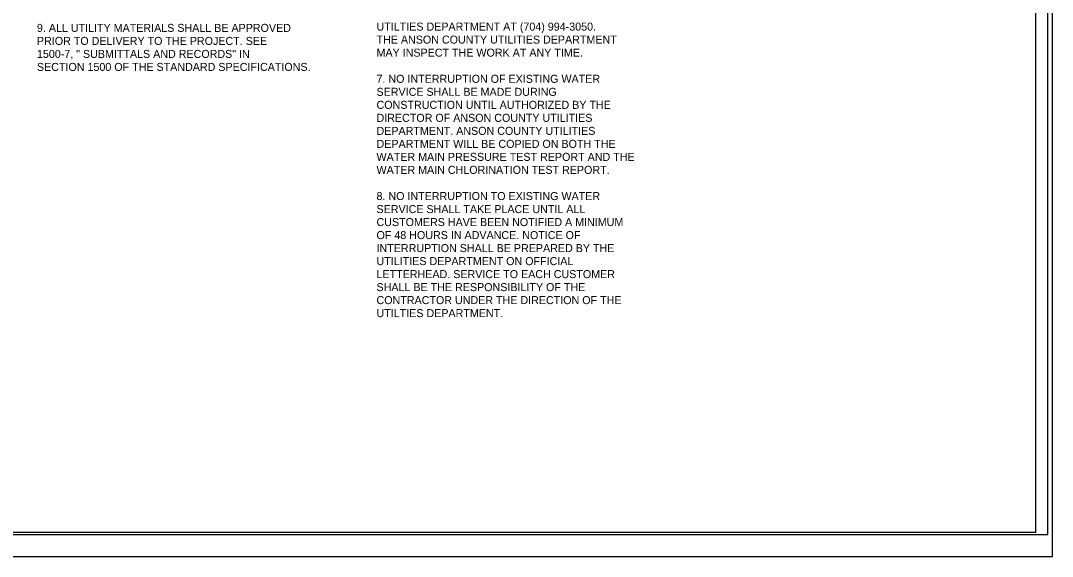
# Model space of a CAD drawing. Extents: x 0 to 674, y 0 to 440.
# Drawn here: x 248.2 to 673.6, y 0 to 220.9 of the extents above; entities that cross this region are included whole.
import ezdxf

# ---------------------------------------------------------------- set-up
doc = ezdxf.new("R2010")
doc.units = 0
for name, color, linetype in [('General Text and Text Box and Leader Line', 7, 'Continuous'), ('Sheet Plot Border Inside CELL', 7, 'Continuous'), ('Sheet Plot Border Outside CELL', 7, 'Continuous'), ('UC Notes and Details Sheet 34 CELL', 7, 'Continuous')]:
    doc.layers.add(name, color=color, linetype=linetype)

msp = doc.modelspace()

# ---------------------------------------------------------------- linework, layer by layer
at = {"layer": 'Sheet Plot Border Inside CELL'}
msp.add_lwpolyline([(671.8, 431.01), (5.2, 431.01), (5.2, 8.97), (671.8, 8.97)], close=True, dxfattribs=at)
at = {"layer": 'Sheet Plot Border Outside CELL'}
msp.add_lwpolyline([(673.6, 440), (0, 440), (0, 0), (673.6, 0)], close=True, dxfattribs=at)
at = {"layer": 'UC Notes and Details Sheet 34 CELL'}
msp.add_lwpolyline([(666.8, 430), (66.8, 430), (66.8, 10), (666.8, 10)], close=True, dxfattribs=at)

# ---------------------------------------------------------------- texts
at = {"layer": 'General Text and Text Box and Leader Line'}
for s, p in [('9. ALL UTILITY MATERIALS SHALL BE APPROVED ', (254.96, 216.22)), ('UTILTIES DEPARTMENT AT (704) 994-3050. ', (394.96, 216.75)), ('PRIOR TO DELIVERY TO THE PROJECT. SEE ', (254.96, 210.85)), ('THE ANSON COUNTY UTILITIES DEPARTMENT ', (394.96, 211.39)), ('1500-7, " SUBMITTALS AND RECORDS" IN ', (254.96, 205.49)), ('MAY INSPECT THE WORK AT ANY TIME.', (394.96, 206.02)), ('SECTION 1500 OF THE STANDARD SPECIFICATIONS.', (254.96, 200.13)), ('7. NO INTERRUPTION OF EXISTING WATER ', (394.96, 195.22)), ('SERVICE SHALL BE MADE DURING ', (394.96, 189.86)), ('CONSTRUCTION UNTIL AUTHORIZED BY THE ', (394.96, 184.5)), ('DIRECTOR OF ANSON COUNTY UTILITIES ', (394.96, 179.14)), ('DEPARTMENT. ANSON COUNTY UTILITIES ', (394.96, 173.77)), ('DEPARTMENT WILL BE COPIED ON BOTH THE ', (394.96, 168.41)), ('WATER MAIN PRESSURE TEST REPORT AND THE ', (394.96, 163.05)), ('WATER MAIN CHLORINATION TEST REPORT.', (394.96, 157.69)), ('8. NO INTERRUPTION TO EXISTING WATER ', (394.96, 146.89)), ('SERVICE SHALL TAKE PLACE UNTIL ALL ', (394.96, 141.52)), ('CUSTOMERS HAVE BEEN NOTIFIED A MINIMUM ', (394.96, 136.16)), ('OF 48 HOURS IN ADVANCE. NOTICE OF ', (394.96, 130.8)), ('INTERRUPTION SHALL BE PREPARED BY THE ', (394.96, 125.44)), ('UTILITIES DEPARTMENT ON OFFICIAL ', (394.96, 120.07)), ('LETTERHEAD. SERVICE TO EACH CUSTOMER ', (394.96, 114.71)), ('SHALL BE THE RESPONSIBILITY OF THE ', (394.96, 109.35)), ('CONTRACTOR UNDER THE DIRECTION OF THE ', (394.96, 103.99)), ('UTILTIES DEPARTMENT.', (394.96, 98.62))]:
    msp.add_text(s, height=3.3, rotation=360, dxfattribs=at).set_placement(p)

doc.saveas('drawing.dxf')
